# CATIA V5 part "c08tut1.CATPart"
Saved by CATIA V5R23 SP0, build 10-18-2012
Part number: Part1
Bounding box of the stored display mesh (mm): x -175 to 175, y -250 to 250, z -8 to 100
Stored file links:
  D:\APS\CATIA V5-6R-2013-Project\CATIA V5-6R2013_partfiles\Tutorials\c08_catia_v5-6r2013_tut\c08tut1.CATPart
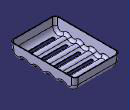
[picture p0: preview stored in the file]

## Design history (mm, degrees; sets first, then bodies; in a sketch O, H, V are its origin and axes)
Body1 (main body)
  Sketch1 on yz-plane, origin (0, 0, 0), H (0, 1, 0), V (0, 0, 1)
    line L1 (250, 100) -> (250, 0)
    line L2 (250, 0) -> (-250, 0)
    line L3 (-250, 0) -> (-250, 100)
    line L4 (-250, 100) -> (250, 100)
    length L1 = 100
    length L4 = 500
    distance V L1 = 250
    vertical: L1 V, L3 V
    horizontal: L2 H, L4 H
    coincidence: H L2
  Pad1: profile Sketch1, direction (1, 0, 0), length 175, mirrored extent
  Draft1: Angle 5, Neutral face of Pad1 from Sketch1.L4, PullDir face of Pad1 from Sketch1.L4
  Sketch2 on yz-plane, origin (0, 0, 0), H (0, 1, 0), V (0, 0, 1)
    arc A1 centre (-195.4346, 50) radius 50 from (-245.2443, 45.6422) to (-162.8621, 12.0654) ccw
    reference projected line E1 (-236.9099, -49.6202) -> (-245.6588, 50.3798) from edge [end face of Pad1 | face of Pad1 from Sketch1.L3]
    reference projected line E2 (241.2511, 0) -> (-241.2511, 0) from edge [end face of Pad1 | face of Pad1 from Sketch1.L2]
    arc A2 centre (195.4346, 50) radius 50 from (162.8621, 12.0654) to (245.2443, 45.6422) ccw
    reference projected line E3 (241.2511, 0) -> (-241.2511, 0) from edge [end face of Pad1 | face of Pad1 from Sketch1.L2]
    reference projected line E4 (245.6588, 50.3798) -> (236.9099, -49.6202) from edge [end face of Pad1 | face of Pad1 from Sketch1.L1]
    arc A3 centre (-146.5759, -6.902) radius 25 from (-162.8621, 12.0654) to (-130.2897, 12.0654) cw
    arc A4 centre (-48.8586, -6.902) radius 25 from (-65.1449, 12.0654) to (-32.5724, 12.0654) cw
    point P9 (-48.8586, -6.902)
    arc A5 centre (48.8586, -6.902) radius 25 from (32.5724, 12.0654) to (65.1449, 12.0654) cw
    point P12 (48.8586, -6.902)
    arc A6 centre (146.5759, -6.902) radius 25 from (130.2897, 12.0654) to (162.8621, 12.0654) cw
    construction line L1 (-146.5759, -6.902) -> (146.5759, -6.902)
    point P18 (245.2443, 45.6422)
    arc A7 centre (97.7173, 50) radius 50 from (65.1449, 12.0654) to (130.2897, 12.0654) ccw
    arc A8 centre (0, 50) radius 50 from (-32.5724, 12.0654) to (32.5724, 12.0654) ccw
    point P19 (-245.2443, 45.6422)
    arc A9 centre (-97.7173, 50) radius 50 from (-130.2897, 12.0654) to (-65.1449, 12.0654) ccw
    reference projected line E5 (245.6588, 50.3798) -> (236.9099, -49.6202) from edge [end face of Pad1 | face of Pad1 from Sketch1.L1]
    reference projected line E6 (-236.9099, -49.6202) -> (-245.6588, 50.3798) from edge [end face of Pad1 | face of Pad1 from Sketch1.L3]
    reference projected line E7 (241.2511, 0) -> (-241.2511, 0) from edge [end face of Pad1 | face of Pad1 from Sketch1.L2]
    reference projected line E8 (241.2511, 0) -> (-241.2511, 0) from edge [end face of Pad1 | face of Pad1 from Sketch1.L2]
    reference projected line E9 (241.2511, 0) -> (-241.2511, 0) from edge [end face of Pad1 | face of Pad1 from Sketch1.L2]
    radius A3 = 25
    radius A4 = 25
    radius A5 = 25
    radius A6 = 25
    radius A9 = 50
    radius A8 = 50
    radius A7 = 50
    radius A1 = 50
    radius A2 = 50
    tangency: A1 E1, A1 E2, A2 E3, A2 E4, A3 A1, A6 A2, A3 A9, A4 A8, A4 A9, A8 A5, A5 A7, A7 A6, A9 E7, A7 E8, A8 E9
    coincidence: L1 P12, P9 L1, P18 E5, P19 E6
    horizontal: L1 H
  Pocket1: profile Sketch2, direction (-1, 0, 0), through (limit type 3), opposite side through (limit type 3)
  Fillet1: radius 25, on edge [end face of Pad1 | face of Pocket1]; edge [face of Pocket1 | start face of Pad1]
  Shell1: ExtOffset 0, Face face of Pad1 from Sketch1.L4, IntOffset 5
  Sketch3 on xy-plane, origin (0, 0, 0), H (1, 0, 0), V (0, 1, 0)
    construction line L1 (-105, 195.4) -> (105, 195.4)
    point P1 (-105, 195.4)
    line L2 (-105, 207.4) -> (105, 207.4)
    line L3 (105, 183.4) -> (-105, 183.4)
    arc A1 centre (105, 195.4) radius 12 from (105, 207.4) to (105, 183.4) cw
    arc A2 centre (-105, 195.4) radius 12 from (-105, 183.4) to (-105, 207.4) cw
    reference projected line E1 (175, 250) -> (-175, 250) from edge [face of Pad1 from Sketch1.L1 | face of Pad1 from Sketch1.L4]
    length L1 = 210
    distance V P1 = 105
    distance L3 L2 = 24
    distance L1 E1 = 54.6
    horizontal: L1 H
    tangency: A1 L2, A2 L2, A1 L3, A2 L3
  Pocket2: profile Sketch3, direction (0, 0, 1), through (limit type 6)
  RectPattern1: of Pocket2, direction 1 instances 5, spacing 97.7, along edge [face of Shell1 | face of Pad1 from Sketch1.L4]
  Sketch4 on xy-plane, origin (0, 0, 0), H (1, 0, 0), V (0, 1, 0)
    circle A1 centre (-135, -195.4) radius 10
    point P1 (-135, -195.4)
    reference projected line E1 (-175, 250) -> (-175, -250) from edge [start face of Pad1 | face of Pad1 from Sketch1.L4]
    reference projected line E2 (-175, -250) -> (175, -250) from edge [face of Pad1 from Sketch1.L3 | face of Pad1 from Sketch1.L4]
    radius A1 = 10
    distance P1 E1 = 40
    distance E2 P1 = 54.6
  Pad2: profile Sketch4, direction (0, 0, 1), up to the existing solid (limit type 2), opposite side length 8
  RectPattern2: of Pad2, direction 1 instances 2, spacing 390.8, along edge [start face of Pad1 | face of Pad1 from Sketch1.L4] reversed, direction 2 instances 2, spacing 270, along edge [face of Pad1 from Sketch1.L3 | face of Pad1 from Sketch1.L4]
